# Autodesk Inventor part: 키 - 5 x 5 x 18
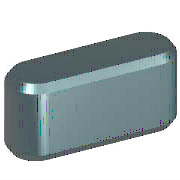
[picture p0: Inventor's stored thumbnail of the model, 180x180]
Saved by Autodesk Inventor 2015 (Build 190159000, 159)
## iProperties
Created: 2012-02
Part Number: 키 - 5 x 5 x 18
Material: 강철, 연강
Description: 키 및 해당 키홈
Document SubType Name: Modeling
Standard: KS B 1311
Designer: mduedu
Standards Organization: KS
Language: ko-KR
Size Designation: 5 x 5 x 18
Categories: <MemberInstance><Categories><Category DisplayName="샤프트 부품" InternalName="7f7aeb1f-a693-4053-b835-cee3144e0d98" Mnemonic="SHFT"><Category DisplayName="키" Interna
Density: 7.86 g/cm^3
Mass: 3.27476 g
Surface Area: 3.57848 cm^2
Volume: 0.416636 cm^3
Appearance: 파란색 - 벽 페인트 - 광택
IsCustomPart: 1
Author: mduedu
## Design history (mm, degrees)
workplane "Work Plane1"
workplane "Work Plane2"
sketch "스케치1"
  geometry: L1 (2.5, 2.5)-(15.5, 2.5); L2 (15.5, -2.5)-(2.5, -2.5); L3 (0, 9.4)-(0, -7.4) reference; L4 (-5, 0)-(30, 0) reference; L5 (18, 0)-(18, 7); A1 r 2.5 centre (2.5, 0) between (2.5, 2.5) and (2.5, -2.5); A2 r 2.5 centre (15.5, 0) between (15.5, -2.5) and (15.5, 2.5)
  constraints: 6 end point, 5 point on circle, 4 tangent, 3 point on line, 2 centre point, 1 horizontal, 1 parallel, 1 perpendicular
  dimensions: "d0" = 2.5 radius of A1 (= 0.5 x PB); "d13" = 2.5 radius of A2 (= 0.5 x PB); "d14" = 18 distance between parallel lines of L5 L3 (= NLG)
extrude "본체1" new body sketch "스케치1" taper "d3" = 0 deg; stored distance "d4" = 10
workplane "Work Plane3"
body "Solid1"
chamfer "모따기1" distance "d8" = 0.4 (= PHH); stored, may be unused: second distance "d9" = 0.4 (= PHH), angle "d15" = 45 deg
other parameters: "d1" = -3 (= -PNT), "d2" = 2 (= PH - PNT), "NLG" = 18 [user parameter; used in 3 equation terms], "PB" = 5 [user parameter; used in 2 equation terms], "PNT" = 3 [user parameter; used in 2 equation terms], "PH" = 5 [user parameter; used in 1 equation term], "PHH" = 0.4 [user parameter; used in 2 equation terms], "d10" = 0, "d16" = 0, "d17" = 0, "d18" = 0, "WDMIN" = 12 [user parameter], "PLB2" = 18 (= NLG) [user parameter], "WDMAX" = 17 [user parameter], "PLB1" = 18 (= NLG) [user parameter], "RR" = 0.16 [user parameter], "PUEB" = 2.3 [user parameter]
